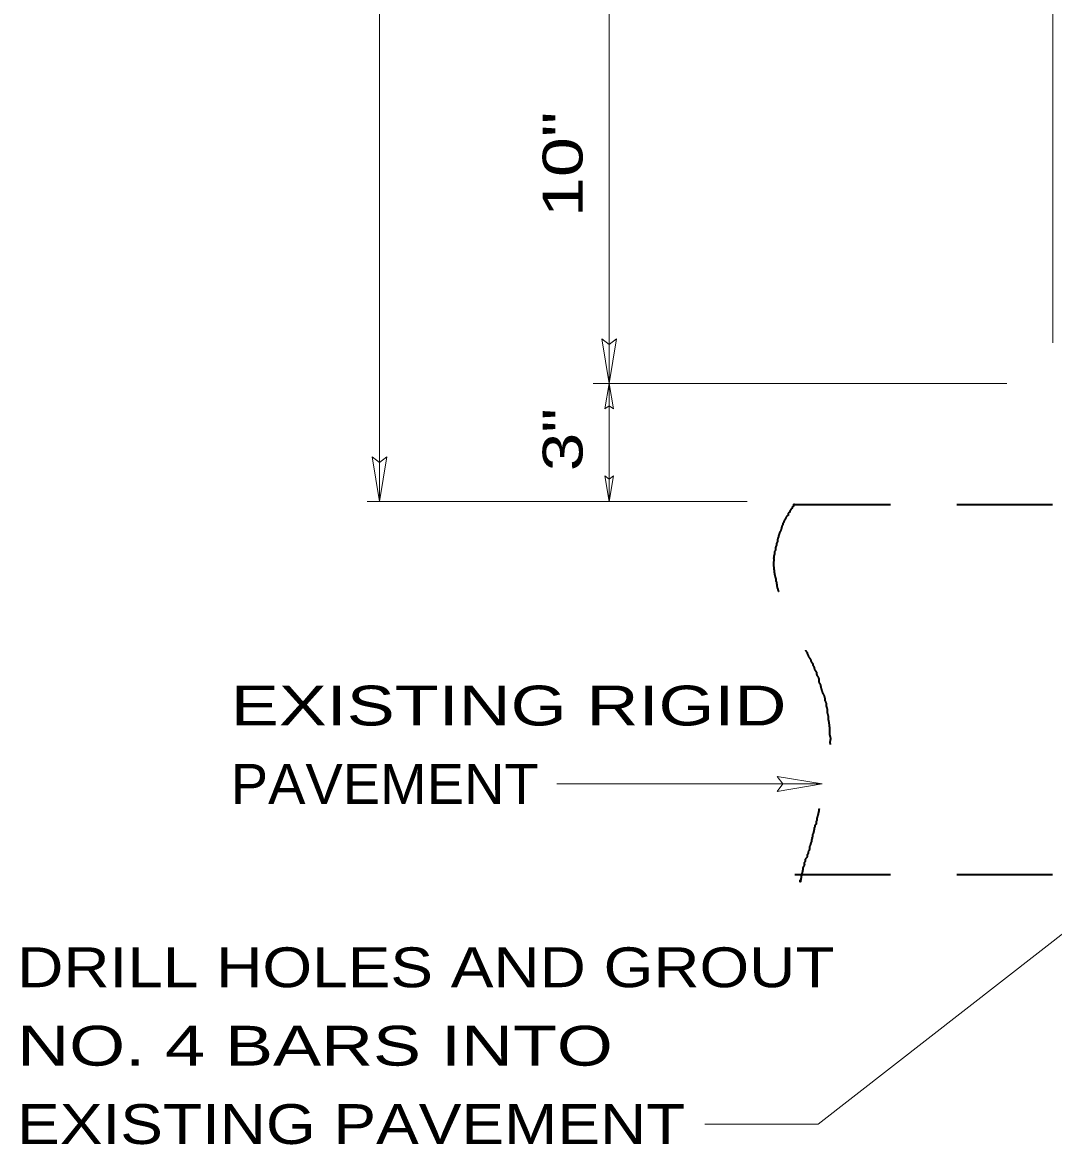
# Model space of a CAD drawing. Extents: x 2.21 to 9.21, y 11.59 to 21.05.
# Drawn here: x 2.386 to 3.939, y 16.972 to 18.662 of the extents above; entities that cross this region are included whole.
import ezdxf
from ezdxf.enums import TextEntityAlignment as Align

# ---------------------------------------------------------------- set-up
doc = ezdxf.new("R2010")
doc.units = 0
doc.header["$LTSCALE"] = 0.024
doc.linetypes.add('LONG_DASHED', pattern=[7.5, 6, -1.5])
for name, color, linetype, lineweight in [('1', 7, 'Continuous', 35), ('10', 7, 'Continuous', 13), ('12', 7, 'Continuous', 53)]:
    doc.layers.add(name, color=color, linetype=linetype, lineweight=lineweight)

msp = doc.modelspace()

# ---------------------------------------------------------------- linework, layer by layer
at = {"layer": '1', "linetype": 'LONG_DASHED'}
for p, q in [((3.5495, 17.936), (3.94117, 17.936)), ((3.5495, 17.37883), (5.47583, 17.37883))]:
    msp.add_line(p, q, dxfattribs=at)
at = {"layer": '10'}
for p, q in [((2.924, 17.9405), (2.924, 19.98033)), ((3.938, 18.17917), (3.938, 18.74583)), ((3.25867, 18.18533), (3.26983, 18.11817)), ((3.25867, 18.18533), (3.26983, 18.177)), ((3.281, 18.18533), (3.26983, 18.11817)), ((3.281, 18.18533), (3.26983, 18.177)), ((3.86883, 18.11817), (3.24583, 18.11817)), ((3.2635, 18.07983), (3.26983, 18.11817)), ((3.27633, 18.07983), (3.26983, 18.11817)), ((3.2635, 18.07983), (3.26983, 18.0845)), ((3.27633, 18.07983), (3.26983, 18.0845)), ((2.91283, 18.00783), (2.924, 17.9405)), ((2.91283, 18.00783), (2.924, 17.99933)), ((2.93533, 18.00783), (2.924, 17.9405)), ((2.93533, 18.00783), (2.924, 17.99933)), ((3.2635, 17.979), (3.26983, 17.9405)), ((3.2635, 17.979), (3.26983, 17.97417)), ((3.27633, 17.979), (3.26983, 17.9405)), ((3.27633, 17.979), (3.26983, 17.97417)), ((3.4775, 17.9405), (2.9055, 17.9405)), ((3.52317, 17.52633), (3.5905, 17.51517)), ((3.52317, 17.52633), (3.53167, 17.51517)), ((3.19117, 17.51517), (3.5905, 17.51517)), ((3.52317, 17.50383), (3.5905, 17.51517)), ((3.52317, 17.50383), (3.53167, 17.51517))]:
    msp.add_line(p, q, dxfattribs=at)
for points in [[(3.26983, 17.9405), (3.26983, 18.11817), (3.26983, 18.76983)], [(3.414, 17.00283), (3.58483, 17.00283), (4.46983, 17.69183)]]:
    msp.add_lwpolyline(points, dxfattribs=at)
at = {"layer": '10', "linetype": 'LONG_DASHED', "lineweight": 35}
for points in [[(3.5495, 17.936), (3.54783, 17.93567), (3.54783, 17.93617), (3.54733, 17.93367), (3.54683, 17.93233), (3.54533, 17.93183), (3.54533, 17.93033), (3.544, 17.929), (3.543, 17.9275), (3.5425, 17.927), (3.542, 17.9245), (3.53967, 17.92267), (3.53967, 17.92017), (3.53767, 17.91833), (3.53483, 17.9135), (3.53383, 17.912), (3.53333, 17.911), (3.5325, 17.90867), (3.532, 17.90817), (3.5315, 17.90717), (3.5315, 17.90567), (3.5305, 17.90417), (3.53, 17.90283), (3.5295, 17.90083), (3.52767, 17.8955), (3.52667, 17.8935), (3.52567, 17.89067), (3.52517, 17.88917), (3.52483, 17.88683), (3.52433, 17.88583), (3.52383, 17.88433), (3.52333, 17.88233), (3.52333, 17.88033), (3.522, 17.877), (3.522, 17.8755), (3.521, 17.87267), (3.5205, 17.86917), (3.5205, 17.86767), (3.519, 17.86483), (3.519, 17.86183), (3.5185, 17.86033), (3.518, 17.858), (3.51767, 17.8545), (3.518, 17.852), (3.51767, 17.85067), (3.5175, 17.84333), (3.519, 17.831), (3.52, 17.8265), (3.5205, 17.825), (3.521, 17.82117), (3.52133, 17.81967), (3.52183, 17.81917), (3.52183, 17.81767), (3.52233, 17.81567), (3.52283, 17.81117), (3.52383, 17.80833), (3.52433, 17.80633), (3.52483, 17.80483), (3.52517, 17.80133), (3.52667, 17.7965), (3.52767, 17.795), (3.528, 17.792), (3.529, 17.79), (3.5295, 17.7885), (3.53, 17.786), (3.531, 17.78267), (3.53283, 17.77867), (3.53383, 17.77717), (3.53483, 17.77417), (3.53567, 17.77267), (3.53567, 17.77117), (3.53767, 17.76817), (3.53817, 17.76667), (3.54, 17.76367), (3.5415, 17.76117), (3.54333, 17.75867), (3.54333, 17.75717), (3.54533, 17.75433), (3.54667, 17.75083), (3.54817, 17.74933), (3.54867, 17.74783), (3.55017, 17.74483), (3.551, 17.74333), (3.5515, 17.74083), (3.553, 17.73933), (3.554, 17.73783), (3.55483, 17.73583), (3.55633, 17.73233), (3.55817, 17.73083), (3.55967, 17.72683), (3.5615, 17.72383), (3.5635, 17.72233), (3.564, 17.7205), (3.565, 17.718), (3.56633, 17.715), (3.56783, 17.713), (3.56833, 17.711)], [(3.56833, 17.711), (3.56917, 17.7095), (3.56967, 17.708), (3.5735, 17.7015), (3.5745, 17.6985), (3.576, 17.697), (3.57683, 17.6935), (3.57783, 17.69217), (3.57883, 17.68867), (3.58067, 17.68517), (3.58217, 17.68267), (3.58217, 17.68117), (3.584, 17.67667), (3.5855, 17.67367), (3.586, 17.66783), (3.58783, 17.66483), (3.58833, 17.66233), (3.58983, 17.6565), (3.59117, 17.6525), (3.59267, 17.6495), (3.5945, 17.6435), (3.5945, 17.64167), (3.5965, 17.63667), (3.5965, 17.63367), (3.5975, 17.63017), (3.59833, 17.62433), (3.59833, 17.62233), (3.59933, 17.6185), (3.59983, 17.612), (3.60033, 17.6095), (3.60133, 17.60217), (3.60167, 17.59917), (3.60167, 17.59183), (3.60217, 17.5875), (3.60317, 17.583), (3.60267, 17.5805), (3.60267, 17.57517), (3.60317, 17.57267), (3.60267, 17.56933), (3.60267, 17.56733), (3.60317, 17.56483), (3.60267, 17.56333), (3.60317, 17.56183), (3.60217, 17.5585), (3.60217, 17.557), (3.60167, 17.55567), (3.60083, 17.55317), (3.60133, 17.55167), (3.60083, 17.54967), (3.60033, 17.54683), (3.59883, 17.541), (3.59783, 17.5375), (3.59733, 17.53417), (3.5965, 17.53167), (3.596, 17.52733), (3.5955, 17.52433), (3.5945, 17.521), (3.5945, 17.5185), (3.59267, 17.51017), (3.59167, 17.50533), (3.59117, 17.5005), (3.59067, 17.498), (3.59017, 17.497), (3.58933, 17.4935), (3.58933, 17.49217), (3.58883, 17.49017), (3.58833, 17.48867), (3.58833, 17.48733), (3.58783, 17.48533), (3.58733, 17.48383), (3.58683, 17.48183), (3.58683, 17.48), (3.58633, 17.4785), (3.58583, 17.4765), (3.58583, 17.475), (3.58533, 17.4735), (3.585, 17.47217), (3.5845, 17.46917), (3.584, 17.46767), (3.583, 17.46433), (3.5825, 17.46233), (3.5825, 17.46083), (3.582, 17.459), (3.5815, 17.458), (3.5815, 17.457), (3.58117, 17.454), (3.57967, 17.45267), (3.57967, 17.45067), (3.57867, 17.44917), (3.57867, 17.44633), (3.57817, 17.44583), (3.57817, 17.44433), (3.57767, 17.44283), (3.57717, 17.4405), (3.57633, 17.439), (3.57633, 17.436), (3.57533, 17.43417)], [(3.57533, 17.43417), (3.57533, 17.43267), (3.57483, 17.43117), (3.57483, 17.42967), (3.57333, 17.42533), (3.573, 17.42383), (3.5715, 17.4195), (3.5715, 17.418), (3.57, 17.41367), (3.5695, 17.41317), (3.5695, 17.41217), (3.56867, 17.40917), (3.56817, 17.40883), (3.56817, 17.40783), (3.56667, 17.40333), (3.56517, 17.4015), (3.56517, 17.3995), (3.56483, 17.39817), (3.56383, 17.39667), (3.56383, 17.39367), (3.56233, 17.39033), (3.5615, 17.38733), (3.5615, 17.38583), (3.561, 17.384), (3.5605, 17.381), (3.56, 17.3795), (3.56, 17.378), (3.5595, 17.37717), (3.559, 17.37567), (3.559, 17.37367), (3.5585, 17.37217), (3.5585, 17.37083), (3.55817, 17.36983), (3.55817, 17.36883), (3.55767, 17.36733), (3.55767, 17.36883), (3.55717, 17.37033)]]:
    msp.add_spline(points, degree=3, dxfattribs=at)

# ---------------------------------------------------------------- texts
at = {"layer": '12'}
for s, width, p in [('10"', 1.35, (3.22983, 18.44813)), ('3"', 1.3, (3.22983, 18.03354))]:
    msp.add_text(s, height=0.06001, rotation=90, dxfattribs=dict(at, width=width)).set_placement(p, align=Align.CENTER)
for s, width, p in [('EXISTING RIGID', 1.35, (2.70017, 17.60308)), ('PAVEMENT', 1.05, (2.70017, 17.48508)), ('DRILL HOLES AND GROUT', 1.2, (2.3785, 17.20892)), ('NO. 4 BARS INTO', 1.35, (2.3785, 17.09083)), ('EXISTING PAVEMENT', 1.2, (2.3785, 16.97283))]:
    msp.add_text(s, height=0.06001, dxfattribs=dict(at, width=width)).set_placement(p)

doc.saveas('drawing.dxf')
